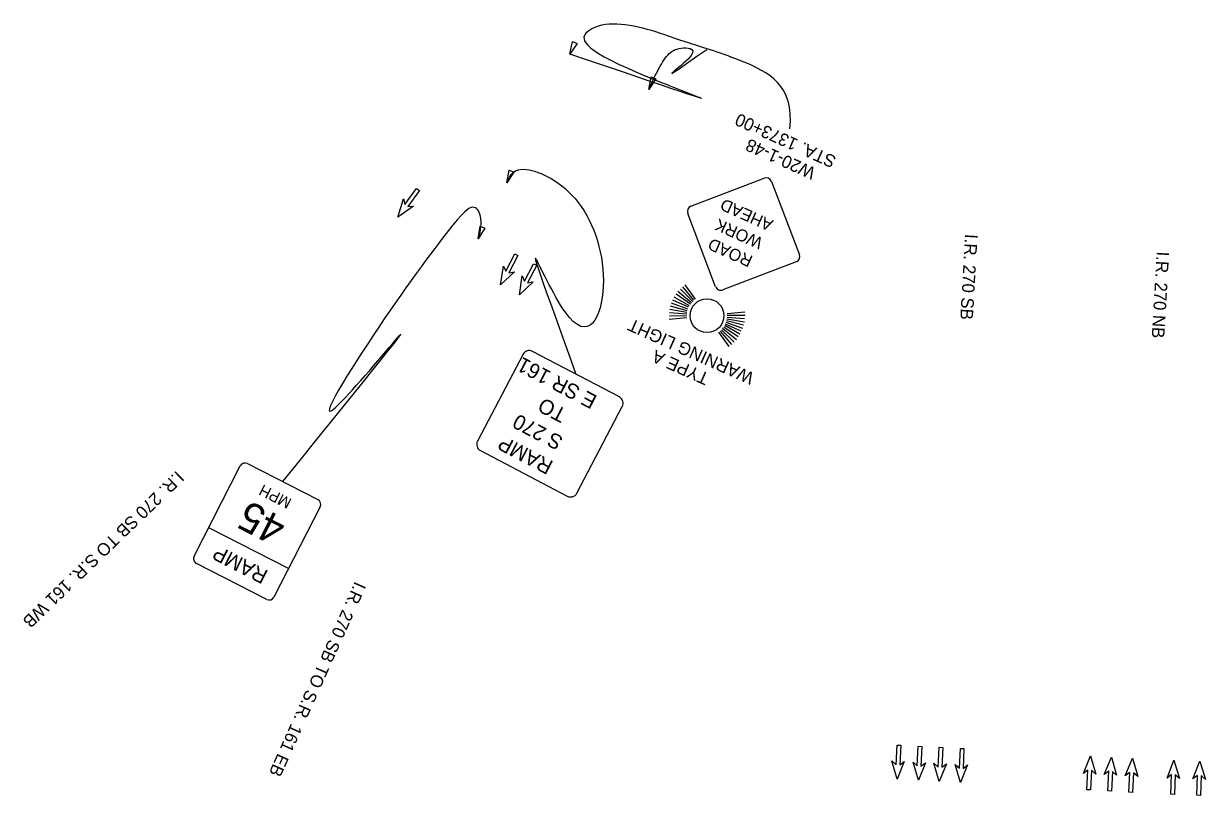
# Model space of a CAD drawing. Extents: x 217413 to 218294, y 612415 to 614235.
# Drawn here: x 217485 to 218144, y 613269 to 613699 of the extents above; entities that cross this region are included whole.
import ezdxf

# ---------------------------------------------------------------- set-up
doc = ezdxf.new("R2010")
doc.units = 0
for name, color, linetype in [('MT_P_Cells', 7, 'Continuous'), ('SH_Text', 7, 'Continuous'), ('SN_P_Signs', 7, 'Continuous'), ('SN_P_Text', 7, 'Continuous'), ('SN_X_Public', 7, 'Continuous'), ('TX_P_Misc', 7, 'Continuous')]:
    doc.layers.add(name, color=color, linetype=linetype)

msp = doc.modelspace()

# ---------------------------------------------------------------- linework, layer by layer
at = {"layer": 'MT_P_Cells'}
for p, q in [((217698.04, 613598.14), (217704.54, 613607.01)), ((217706.15, 613605.83), (217699.65, 613596.96)), ((217704.54, 613607.01), (217706.15, 613605.83)), ((217705.35, 613606.42), (217705.35, 613606.42)), ((217694.11, 613591.1), (217697.23, 613601.21)), ((217702.83, 613597.11), (217694.11, 613591.1)), ((217697.23, 613601.21), (217698.04, 613598.14)), ((217699.65, 613596.96), (217702.83, 613597.11)), ((217694.11, 613591.1), (217694.11, 613591.1)), ((217754.22, 613560.9), (217759.3, 613570.65)), ((217761.08, 613569.72), (217755.99, 613559.97)), ((217759.3, 613570.65), (217761.08, 613569.72)), ((217760.19, 613570.19), (217760.19, 613570.19)), ((217751.41, 613553.34), (217752.95, 613563.81)), ((217752.95, 613563.81), (217754.22, 613560.9)), ((217764.7, 613555.37), (217769.79, 613565.12)), ((217771.56, 613564.2), (217766.48, 613554.44)), ((217769.79, 613565.12), (217771.56, 613564.2)), ((217770.67, 613564.66), (217770.67, 613564.66)), ((217759.11, 613560.6), (217751.41, 613553.34)), ((217755.99, 613559.97), (217759.11, 613560.6)), ((217761.89, 613547.81), (217763.43, 613558.29)), ((217763.43, 613558.29), (217764.7, 613555.37)), ((217751.41, 613553.34), (217751.41, 613553.34)), ((217769.59, 613555.07), (217761.89, 613547.81)), ((217766.48, 613554.44), (217769.59, 613555.07)), ((217761.89, 613547.81), (217761.89, 613547.81)), ((217971.91, 613285.8), (217972.45, 613296.79)), ((217972.45, 613296.79), (217974.45, 613296.69)), ((217973.45, 613296.74), (217973.45, 613296.74)), ((217974.45, 613296.69), (217973.91, 613285.7)), ((217983.72, 613285.17), (217984.26, 613296.15)), ((217984.26, 613296.15), (217986.26, 613296.05)), ((217985.26, 613296.1), (217985.26, 613296.1)), ((217986.26, 613296.05), (217985.71, 613285.07)), ((217995.37, 613284.53), (217995.92, 613295.51)), ((217995.92, 613295.51), (217997.91, 613295.42)), ((217996.91, 613295.47), (217996.91, 613295.47)), ((217997.91, 613295.42), (217997.37, 613284.43)), ((218007.21, 613283.89), (218007.75, 613294.87)), ((218007.75, 613294.87), (218009.75, 613294.78)), ((218008.75, 613294.83), (218008.75, 613294.83)), ((218009.75, 613294.78), (218009.21, 613283.79)), ((217972.51, 613277.76), (217969.54, 613287.92)), ((217969.54, 613287.92), (217971.91, 613285.8)), ((217976.47, 613287.58), (217972.51, 613277.76)), ((217973.91, 613285.7), (217976.47, 613287.58)), ((217984.32, 613277.13), (217981.34, 613287.29)), ((217981.34, 613287.29), (217983.72, 613285.17)), ((217988.28, 613286.94), (217984.32, 613277.13)), ((217985.71, 613285.07), (217988.28, 613286.94)), ((217995.98, 613276.49), (217993, 613286.65)), ((217993, 613286.65), (217995.37, 613284.53)), ((218076.31, 613280.95), (218080.33, 613290.74)), ((218080.33, 613290.74), (218080.33, 613290.74)), ((218080.33, 613290.74), (218083.25, 613280.57)), ((218087.94, 613280.29), (218091.95, 613290.08)), ((218091.95, 613290.08), (218091.95, 613290.08)), ((218091.95, 613290.08), (218094.87, 613279.91)), ((218099.69, 613279.6), (218103.7, 613289.4)), ((218103.7, 613289.4), (218103.7, 613289.4)), ((218103.7, 613289.4), (218106.62, 613279.22)), ((218122.96, 613278.38), (218126.78, 613288.26)), ((218126.78, 613288.26), (218126.78, 613288.26)), ((218126.78, 613288.26), (218129.9, 613278.14)), ((218137.39, 613277.87), (218141.21, 613287.75)), ((218141.21, 613287.75), (218141.21, 613287.75)), ((218141.21, 613287.75), (218144.33, 613277.63)), ((217999.94, 613286.31), (217995.98, 613276.49)), ((217997.37, 613284.43), (217999.94, 613286.31)), ((218007.81, 613275.85), (218004.84, 613286.01)), ((218004.84, 613286.01), (218007.21, 613283.89)), ((218011.77, 613285.67), (218007.81, 613275.85)), ((218009.21, 613283.79), (218011.77, 613285.67)), ((218078.89, 613282.81), (218076.31, 613280.95)), ((218078.29, 613271.83), (218078.89, 613282.81)), ((218080.89, 613282.7), (218080.28, 613271.72)), ((218083.25, 613280.57), (218080.89, 613282.7)), ((218090.51, 613282.15), (218087.94, 613280.29)), ((218089.91, 613271.17), (218090.51, 613282.15)), ((218092.51, 613282.04), (218091.91, 613271.06)), ((218094.87, 613279.91), (218092.51, 613282.04)), ((218102.27, 613281.47), (218099.69, 613279.6)), ((218101.66, 613270.48), (218102.27, 613281.47)), ((218104.26, 613281.36), (218103.66, 613270.37)), ((218106.62, 613279.22), (218104.26, 613281.36)), ((218125.5, 613280.29), (218122.96, 613278.38)), ((218125.12, 613269.3), (218125.5, 613280.29)), ((218127.5, 613280.23), (218127.12, 613269.23)), ((218129.9, 613278.14), (218127.5, 613280.23)), ((218139.93, 613279.79), (218137.39, 613277.87)), ((218139.55, 613268.79), (218139.93, 613279.79)), ((217972.51, 613277.76), (217972.51, 613277.76)), ((217984.32, 613277.13), (217984.32, 613277.13)), ((217995.98, 613276.49), (217995.98, 613276.49)), ((218007.81, 613275.85), (218007.81, 613275.85)), ((218141.93, 613279.72), (218141.55, 613268.72)), ((218144.33, 613277.63), (218141.93, 613279.72)), ((218080.28, 613271.72), (218078.29, 613271.83)), ((218079.28, 613271.77), (218079.28, 613271.77)), ((218091.91, 613271.06), (218089.91, 613271.17)), ((218090.91, 613271.11), (218090.91, 613271.11)), ((218103.66, 613270.37), (218101.66, 613270.48)), ((218102.66, 613270.43), (218102.66, 613270.43)), ((218127.12, 613269.23), (218125.12, 613269.3)), ((218126.12, 613269.27), (218126.12, 613269.27)), ((218141.55, 613268.72), (218139.55, 613268.79)), ((218140.55, 613268.76), (218140.55, 613268.76))]:
    msp.add_line(p, q, dxfattribs=at)
at = {"layer": 'SH_Text'}
for points in [[(217791.52, 613688.91), (217794.09, 613687.81), (217790.05, 613681.93)], [(217835.33, 613669.22), (217837.94, 613668.2), (217834.1, 613662.19)], [(217756.17, 613617.16), (217758.77, 613616.15), (217754.93, 613610.13)], [(217740.07, 613586.02), (217742.68, 613585), (217738.83, 613578.99)]]:
    msp.add_lwpolyline(points, close=True, dxfattribs=at)
for points in [[(217912.61, 613640.26), (217915.58, 613664.74), (217884.22, 613679.8), (217855, 613688.27), (217835.65, 613695.5), (217815.63, 613699.91), (217799.48, 613696.98), (217790.05, 613681.93), (217912.61, 613640.26), (217790.05, 613681.93)], [(217834.1, 613662.19), (217835.98, 613666.83), (217839.75, 613674.4), (217845.08, 613683.2), (217852.05, 613686.12), (217866.38, 613684.53), (217834.1, 613662.19), (217866.38, 613684.53)], [(217754.93, 613610.13), (217756.81, 613614.77), (217760.59, 613622.35), (217798.14, 613605.41), (217815.08, 613551.55), (217793.4, 613503.54), (217754.93, 613610.13), (217793.4, 613503.54)], [(217738.83, 613578.99), (217740.71, 613583.63), (217740.89, 613592.87), (217736.48, 613598.45), (217728.29, 613592.89), (217676.38, 613521.59), (217629.88, 613443.62), (217738.83, 613578.99), (217629.88, 613443.62)]]:
    msp.add_open_spline(points, degree=3, dxfattribs=at)
at = {"layer": 'SN_P_Signs'}
for points in [[(217857.53, 613597.21), (217898.41, 613612.79)], [(217902.44, 613610.98), (217918.02, 613570.1)], [(217871.3, 613552.3), (217855.72, 613593.18)], [(217916.21, 613566.07), (217875.33, 613550.49)]]:
    msp.add_lwpolyline(points, dxfattribs=at)
for centre, start, end in [((217899.52, 613609.87), 20.85974, 110.85974), ((217858.64, 613594.29), 110.85974, 200.85974), ((217915.1, 613568.99), 290.85974, 20.85974), ((217874.22, 613553.41), 200.85974, 290.85974)]:
    msp.add_arc(centre, 3.12, start, end, dxfattribs=at)
at = {"layer": 'SN_X_Public'}
for p, q in [((217580.51, 613402.05), (217606.26, 613452.35)), ((217610.29, 613453.65), (217649.46, 613433.6)), ((217650.76, 613429.56), (217625.01, 613379.27)), ((217633.14, 613395.14), (217588.64, 613417.93)), ((217620.98, 613377.96), (217581.81, 613398.02))]:
    msp.add_line(p, q, dxfattribs=at)
for points in [[(217763.92, 613514.6), (217738.51, 613466.17)], [(217817.62, 613490.84), (217769.19, 613516.24)], [(217793.86, 613437.14), (217819.26, 613485.57)], [(217740.16, 613460.9), (217788.58, 613435.49)]]:
    msp.add_lwpolyline(points, dxfattribs=at)
for centre, radius, start, end in [((217767.38, 613512.79), 3.91, 62.31804, 152.31804), ((217815.8, 613487.38), 3.91, 332.31804, 62.31804), ((217741.97, 613464.36), 3.91, 152.31804, 242.31804), ((217608.93, 613450.98), 3, 62.88752, 152.88752), ((217648.09, 613430.93), 3, 332.88752, 62.88752), ((217790.4, 613438.95), 3.91, 242.31804, 332.31804), ((217583.18, 613400.69), 3, 152.88752, 242.88752), ((217622.34, 613380.63), 3, 242.88752, 332.88752)]:
    msp.add_arc(centre, radius, start, end, dxfattribs=at)
at = {"layer": 'TX_P_Misc'}
for p, q in [((217858.49, 613544.11), (217851.62, 613550.85)), ((217859.21, 613544.79), (217852.91, 613552.17)), ((217860, 613545.37), (217854.34, 613553.34)), ((217856.21, 613540.82), (217847.38, 613544.84)), ((217856.66, 613541.7), (217848.15, 613546.53)), ((217857.23, 613542.54), (217849.21, 613548.06)), ((217857.82, 613543.34), (217850.29, 613549.56)), ((217855.19, 613536.96), (217845.48, 613537.73)), ((217855.31, 613537.94), (217845.72, 613539.56)), ((217855.49, 613538.92), (217846.18, 613541.36)), ((217855.84, 613539.83), (217846.76, 613543.11)), ((217887.5, 613538.04), (217877.73, 613537.15)), ((217855.23, 613534.93), (217845.43, 613533.99)), ((217855.17, 613535.96), (217845.5, 613535.87)), ((217884.76, 613525.83), (217876.34, 613530.65)), ((217885.48, 613527.48), (217876.73, 613531.46)), ((217886.46, 613529.04), (217877.14, 613532.31)), ((217886.76, 613530.86), (217877.39, 613533.23)), ((217887.39, 613532.58), (217877.57, 613534.19)), ((217887.46, 613534.42), (217877.72, 613535.19)), ((217887.66, 613536.24), (217877.77, 613536.19)), ((217878.86, 613518.95), (217873.09, 613526.97)), ((217880.27, 613520.12), (217873.91, 613527.59)), ((217881.61, 613521.37), (217874.63, 613528.28)), ((217882.86, 613522.7), (217875.2, 613529.01)), ((217883.77, 613524.31), (217875.84, 613529.79))]:
    msp.add_line(p, q, dxfattribs=at)
msp.add_circle((217866.47, 613536.13), 9.45, dxfattribs=at)

# ---------------------------------------------------------------- texts
at = {"layer": 'SH_Text'}
for s, rotation, p in [('I.R. 270 SB', 266.71552, (218010.4, 613581.8)), ('I.R. 270 NB', 266.71552, (218117.2, 613572.04)), ('I.R. 270 SB TO S.R. 161 WB', 224.06911, (217570.72, 613450.06)), ('I.R. 270 SB TO S.R. 161 EB', 245.8007, (217670.25, 613388.38))]:
    msp.add_text(s, height=7, rotation=rotation, dxfattribs=at).set_placement(p)
at = {"layer": 'SN_P_Signs'}
for s, p in [('AHEAD', (217903.87, 613589.08)), ('WORK', (217898.19, 613579.08)), ('ROAD', (217892.51, 613569.06))]:
    msp.add_text(s, height=6.663, rotation=155.85974, dxfattribs=at).set_placement(p)
at = {"layer": 'SN_P_Text'}
for s, p in [('STA. 1373+00', (217939.07, 613624.61)), ('W20-1-48', (217927.61, 613618.24)), ('WARNING LIGHT', (217893.34, 613503.87)), ('TYPE A', (217868.29, 613503.59))]:
    msp.add_text(s, height=7, rotation=155.85974, dxfattribs=at).set_placement(p)
at = {"layer": 'SN_X_Public'}
for s, height, rotation, p in [('E SR 161', 8.333, 152.31804, (217805.84, 613491.14)), ('TO', 8.333, 152.31804, (217788.88, 613483.56)), ('S 270', 8.333, 152.31804, (217786.9, 613468.14)), ('RAMP', 8.333, 152.31804, (217781.34, 613454.59)), ('MPH', 6.25, 152.88752, (217635.41, 613433.77)), ('45', 16.665, 152.88752, (217632.96, 613422.15)), ('RAMP', 8.333, 152.88752, (217622.35, 613393.65))]:
    msp.add_text(s, height=height, rotation=rotation, dxfattribs=at).set_placement(p)

doc.saveas('drawing.dxf')
